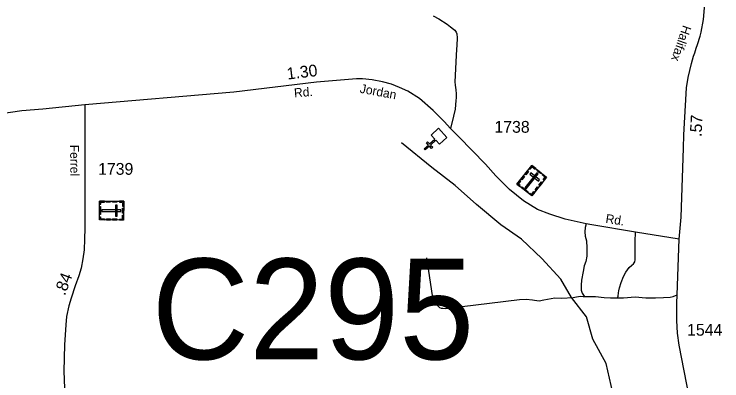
# Model space of a CAD drawing. Extents: x 2220236 to 2384410, y 720751 to 894131.
# Drawn here: x 2333123 to 2340601, y 767554 to 771434 of the extents above; entities that cross this region are included whole.
import ezdxf

# ---------------------------------------------------------------- set-up
doc = ezdxf.new("R2010")
doc.units = 0
for name, color, linetype in [('Exist Cultural Cemetery CELL', 7, 'Continuous'), ('Exist Cultural Church CELL', 7, 'Continuous'), ('Exist Hydrographic Creek Single Shore', 7, 'Continuous'), ('Exist Road Non-System Type 51', 7, 'Continuous'), ('Exist Road Secondary Mileage Hundredths English Label', 7, 'Continuous'), ('Exist Road Secondary Structure Culvert Number Label', 7, 'Continuous'), ('Exist Road Secondary Type 51 Attributed', 7, 'Continuous'), ('Exist Road Secondary Type 51 Label', 7, 'Continuous'), ('Exist Road Secondary Type 51 Number Label', 7, 'Continuous')]:
    doc.layers.add(name, color=color, linetype=linetype)

msp = doc.modelspace()

# ---------------------------------------------------------------- linework, layer by layer
at = {"layer": 'Exist Cultural Cemetery CELL'}
for points in [[(2338593.6, 769833.4), (2338749.7, 769709.8), (2338591.8, 769510.1), (2338435.6, 769633.7)], [(2338566.7, 769799.4), (2338575.6, 769792.4), (2338595.6, 769817.6), (2338627.4, 769792.4), (2338634.3, 769801.2), (2338593.6, 769833.4)], [(2338651.7, 769787.4), (2338692.3, 769755.2), (2338685.3, 769746.3), (2338644.6, 769778.5)], [(2338479, 769688.5), (2338505.9, 769722.5), (2338514.8, 769715.5), (2338487.9, 769681.5)], [(2338660.9, 769742.7), (2338646.3, 769754.3), (2338520.5, 769595.3), (2338535.1, 769583.7)], [(2338520.7, 769741.3), (2338547.6, 769775.2), (2338556.5, 769768.2), (2338529.6, 769734.2)], [(2338583.4, 769754.7), (2338571.8, 769740), (2338664.1, 769667), (2338675.7, 769681.6)], [(2338722.9, 769675.8), (2338714, 769682.8), (2338734, 769708.1), (2338702.2, 769733.2), (2338709.1, 769742), (2338749.8, 769709.8)], [(2338461.6, 769613.2), (2338468.7, 769622.2), (2338451.5, 769635.9), (2338476.5, 769667.5), (2338467.8, 769674.5), (2338435.6, 769633.8)], [(2338668.6, 769625.6), (2338695.5, 769659.5), (2338704.4, 769652.5), (2338677.5, 769618.5)], [(2338487.8, 769607), (2338554.4, 769554.4), (2338547.3, 769545.4), (2338480.7, 769598.1)], [(2338627.7, 769573.9), (2338654.6, 769607.8), (2338663.5, 769600.8), (2338636.6, 769566.8)], [(2338565.8, 769530.7), (2338572.9, 769539.7), (2338590.2, 769526.1), (2338615.2, 769557.8), (2338624, 769550.8), (2338591.8, 769510.1)], [(2334280.6, 769453.6), (2334279.7, 769254.5), (2334025.1, 769255.7), (2334026, 769454.8)], [(2334025.9, 769421.7), (2334037.4, 769421.6), (2334037.5, 769443.6), (2334077.9, 769443.5), (2334077.9, 769454.6), (2334026, 769454.8)], [(2334095.9, 769454.5), (2334139.2, 769454.3), (2334139.2, 769442.9), (2334095.9, 769443.1)], [(2334163.1, 769454.2), (2334206.5, 769454), (2334206.4, 769442.6), (2334163.1, 769442.8)], [(2334212.4, 769413.1), (2334193.7, 769413.2), (2334193.2, 769295.5), (2334211.8, 769295.4)], [(2334237.3, 769453.8), (2334237.2, 769442.5), (2334269.4, 769442.3), (2334269.2, 769401.8), (2334280.4, 769401.7), (2334280.6, 769453.6)], [(2334037.2, 769397.3), (2334036.8, 769312.4), (2334025.4, 769312.4), (2334025.8, 769397.3)], [(2334250.8, 769344.7), (2334250.9, 769363.4), (2334048.1, 769364.3), (2334048, 769345.6)], [(2334280.3, 769379.5), (2334280, 769327.7), (2334268.6, 769327.8), (2334268.9, 769379.6)], [(2334025.2, 769288.8), (2334036.7, 769288.8), (2334036.6, 769266.8), (2334077, 769266.6), (2334077, 769255.4), (2334025.1, 769255.7)], [(2334097.4, 769266.7), (2334140.7, 769266.5), (2334140.7, 769255.1), (2334097.4, 769255.3)], [(2334163.3, 769266.4), (2334206.6, 769266.2), (2334206.6, 769254.8), (2334163.3, 769255)], [(2334236.4, 769254.7), (2334236.4, 769266), (2334268.6, 769265.9), (2334268.8, 769306.4), (2334279.9, 769306.4), (2334279.7, 769254.5)]]:
    msp.add_lwpolyline(points, close=True, dxfattribs=at)
at = {"layer": 'Exist Cultural Church CELL'}
msp.add_lwpolyline([(2337618.5, 770057.7), (2337579.9, 770099.5), (2337523.9, 770047.9), (2337545.6, 770024.4), (2337533.9, 770013.5), (2337512.2, 770037), (2337467.9, 769996.3), (2337457.1, 770008.1), (2337501.3, 770048.8), (2337479.6, 770072.3), (2337491.3, 770083.2), (2337513, 770059.7), (2337569, 770111.3), (2337530, 770153.7), (2337608.2, 770225.9), (2337696.8, 770129.9)], close=True, dxfattribs=at)
at = {"layer": 'Exist Hydrographic Creek Single Shore'}
msp.add_lwpolyline([(2339448.1, 767425.7), (2339378.7, 767736.5), (2339237.2, 767993.7), (2339171.5, 768229.3), (2339013.9, 768435.4), (2338899.7, 768631), (2338698.5, 768847.6), (2338484.9, 769051), (2338266.3, 769203.9), (2338009.3, 769417.8), (2337784.5, 769620.7), (2337536.1, 769809.9), (2337216.9, 770071.1)], dxfattribs=at)
at = {"layer": 'Exist Road Non-System Type 51'}
for points in [[(2337551.3, 771416.2), (2337612.3, 771382.4), (2337697.5, 771327.7), (2337732.8, 771300.4), (2337766.6, 771274.7), (2337781, 771263.4), (2337792.3, 771241.7), (2337799.7, 771224), (2337805.2, 771183.8), (2337800.3, 771100.2), (2337798.7, 771061.6), (2337793.9, 770995.7), (2337790.7, 770930.6), (2337785.9, 770855), (2337781, 770718.3), (2337784.3, 770681.3), (2337787.5, 770655.6), (2337790.7, 770631.5), (2337794, 770588.7), (2337794.5, 770546.8), (2337790.8, 770518.8), (2337783.9, 770428.7), (2337764.8, 770352.5), (2337734.4, 770222.2)], [(2339169, 769216.6), (2339157.3, 769174.7), (2339152.1, 769129.2), (2339157.3, 769083.8), (2339169.5, 769036.6), (2339173, 768961.4), (2339174.8, 768874), (2339164.3, 768816.3), (2339146.8, 768770.9), (2339134.6, 768709.7), (2339118.9, 768620.5), (2339113.6, 768564.6), (2339113.6, 768513.9), (2339124.1, 768480.7), (2339139.8, 768459.7), (2339150.5, 768445.4)], [(2339498.2, 768433.4), (2339505, 768451), (2339510.2, 768484.2), (2339511.9, 768506.9), (2339518.9, 768538.4), (2339538.1, 768594.3), (2339562.6, 768657.2), (2339587.1, 768704.4), (2339622, 768753.4), (2339650, 768777.9), (2339667.4, 768791.8), (2339674.4, 768800.6), (2339681.4, 768814.6), (2339686.6, 768833.8), (2339686.6, 768868.8), (2339686.6, 769027.8), (2339688.4, 769128.3)], [(2337478.8, 768855.7), (2337541.7, 768456.7), (2337554, 768420.8), (2337570.3, 768393), (2337596.9, 768349.3), (2337617, 768331.5), (2337634.8, 768324), (2337654.1, 768322.4), (2337684.6, 768320.8), (2338462.4, 768415.7), (2338533.1, 768417.3), (2338599, 768410.9), (2338623.1, 768406), (2338647.2, 768404.4), (2338669.7, 768401.2), (2338721.1, 768409.3), (2338836.8, 768431.8), (2338907.5, 768430.2), (2339031.3, 768436.6), (2339065, 768443.8), (2339108.4, 768448.7), (2339134.1, 768445.4), (2339150.5, 768445.4)], [(2339150.5, 768445.4), (2339155, 768445.4), (2339179.1, 768446.2), (2339201.6, 768447), (2339227.3, 768445.4), (2339265.2, 768445.3), (2339355.9, 768435), (2339423.4, 768433.4), (2339498.2, 768433.4)], [(2339498.2, 768433.4), (2339563.2, 768433.4), (2339685.3, 768441.4), (2339796.2, 768433.4), (2339900.6, 768433.4), (2339985.8, 768435), (2340053.3, 768439.8), (2340085.4, 768447.8), (2340130.4, 768462.3)]]:
    msp.add_lwpolyline(points, dxfattribs=at)
at = {"layer": 'Exist Road Secondary Type 51 Attributed'}
for points in [[(2340149.7, 769052.4), (2340170.6, 769284), (2340186.7, 769700.5), (2340196.3, 770015.6), (2340199.5, 770157.2), (2340228.5, 770654.8), (2340244.5, 770764.2), (2340281.5, 770910.5), (2340302.4, 770987.7), (2340314.8, 771025.8), (2340328.3, 771072), (2340342.6, 771113.9), (2340373.1, 771199.1), (2340383, 771243.6), (2340406.8, 771378.4), (2340414.9, 771458.8), (2340458.3, 772010.4)], [(2333868.9, 770475.5), (2333425.2, 770428.8), (2333204.4, 770411.2), (2332989.9, 770380.1), (2332365, 770309.4), (2332145.2, 770287), (2332083.3, 770284.5), (2331985.4, 770285.3), (2331867.2, 770304.1), (2331759.1, 770324.9), (2331646.9, 770355.8), (2331534.3, 770398.6), (2331421.9, 770447.2), (2331331.4, 770496.3), (2331222.6, 770569.1), (2331113.8, 770647.9), (2331027.3, 770712.8), (2330896.9, 770816.4)], [(2340149.7, 769052.4), (2339688.4, 769128.3), (2339225.7, 769204.4), (2339169, 769216.6), (2338946.1, 769264.7), (2338782.2, 769316.1), (2338653.6, 769367.6), (2338504.2, 769459.3), (2338356.3, 769579.9), (2338214.1, 769724.1), (2338102.8, 769844.8), (2337821.2, 770133.8), (2337734.4, 770222.2), (2337667, 770296.2), (2337549.6, 770415.2), (2337406.6, 770540.6), (2337281.3, 770619.4), (2337194.5, 770658), (2337110.9, 770691.8), (2337016.1, 770715.9), (2336906.9, 770736.8), (2336804, 770748.1), (2336740.3, 770748.1), (2336318.9, 770715.1), (2335442.9, 770608.2), (2333868.9, 770475.5)], [(2333868.9, 770475.5), (2333868.6, 769168.2), (2333866, 769052.2), (2333861.3, 768940.2), (2333848.4, 768844), (2333829.6, 768745.8), (2333806.6, 768663.7), (2333767.7, 768560.4), (2333724.3, 768430.2), (2333700.2, 768345.7), (2333676.1, 768234.8), (2333669, 768146.3), (2333655.5, 767936), (2333647.2, 767655.9), (2333688.1, 766661), (2333683.8, 766077.8)], [(2340254.2, 767386.6), (2340151.3, 767932.5), (2340133.6, 768059.5), (2340128.8, 768125.4), (2340125.6, 768191.4), (2340124, 768275), (2340124, 768376.3), (2340130.4, 768462.3), (2340149.7, 769052.4)]]:
    msp.add_lwpolyline(points, dxfattribs=at)

# ---------------------------------------------------------------- texts
at = {"layer": 'Exist Road Secondary Mileage Hundredths English Label'}
for s, rotation, p in [('1.30', 6.95745, (2336011, 770740.4)), ('.57', 86.67356, (2340385.9, 770132.9)), ('.84', 69.33357, (2333659, 768449.4))]:
    msp.add_text(s, height=125, rotation=rotation, dxfattribs=at).set_placement(p)
at = {"layer": 'Exist Road Secondary Structure Culvert Number Label'}
msp.add_text('C295', height=1066.27, dxfattribs=at).set_placement((2334576.3, 767781))
at = {"layer": 'Exist Road Secondary Type 51 Label'}
for s, rotation, p in [('Halifax', 250.97854, (2340191.4, 771322.7)), ('Jordan', 349.3708, (2336771.1, 770603.2)), ('Rd.', 4.47753, (2336084, 770552.8)), ('Ferrel', 270.42242, (2333714.5, 770051.3)), ('Rd.', 351.60178, (2339368, 769225.9))]:
    msp.add_text(s, height=95, rotation=rotation, dxfattribs=at).set_placement(p)
at = {"layer": 'Exist Road Secondary Type 51 Number Label'}
for s, p in [('1738', (2338198.4, 770178.4)), ('1739', (2334010.5, 769733.8)), ('1544', (2340234.2, 768031.7))]:
    msp.add_text(s, height=125, dxfattribs=at).set_placement(p)

doc.saveas('drawing.dxf')
